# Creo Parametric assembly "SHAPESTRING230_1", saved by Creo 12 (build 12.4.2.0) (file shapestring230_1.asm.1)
Units: Custom; MM, KILOGRAM, SECS

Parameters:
  PTC_WM_ITERATION = "0"
  PTC_WM_VERSION = "-.0"
  PTC_WM_LIFECYCLE_STATE = "In Work"
  PTC_WM_LIFECYCLE = "MO_CADDocument"
  PTC_WM_CREATED_BY = "Maximilian Roepper (Z0017RMS: MO)"
  PTC_WM_CREATED_ON = "18-Sep-26 11:36:42 AM"
  PTC_WM_MODIFIED_BY = "Maximilian Roepper (Z0017RMS: MO)"
  PTC_WM_MODIFIED_ON = "18-Sep-26 11:36:46 AM"
  PDMLINKNUMBER = "PDM000071455062"
  PTC_WM_NAME = "shapestring230_1.asm"
  PTC_WM_NUMBER = "PDM000071455062"

Other parameters: WEIGHT, WEIGHT_FACTOR, WEIGHT_ADD, MC_ERRORS, SUPPLIER, ISPOSITIONINGASSEMBLY

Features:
  1. coordinate system
  2. imported feature
  3. component "SHAPESTRING090_1"
  4. component "SHAPESTRING229_1"

Other named items: DRW_VIEW_ORG, ROUGH-GROB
